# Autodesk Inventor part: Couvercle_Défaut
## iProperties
Shininess: 64.0
Length Units: 11269
Angle Units: 11279
Time Units: 11290
Mass Units: 11283
Length Display Precision: 3
Angle Display Precision: 2
Compacted: True
Part Number: Couvercle_Défaut
Document SubType Name: Modeling
Created: 2006-01
Material: Par défaut
Designer: riri
Density: 0.0
Volumn: 0.0
Area: 0.0
PropertySet Name: Model Information
Control State: 0
Master: False
Checked Out: False
Author: riri
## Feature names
1. Base1
